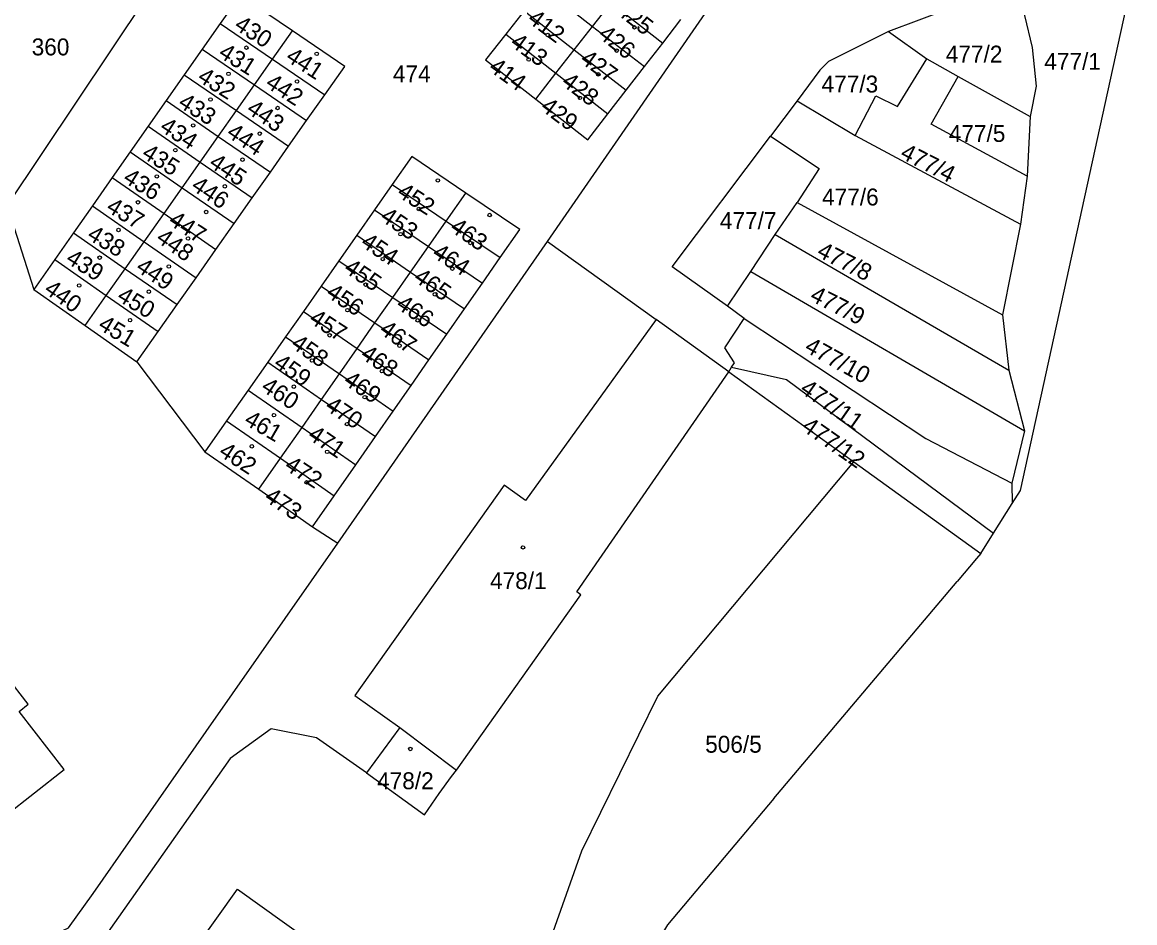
# Model space of a CAD drawing. Extents: x -558358 to -557517, y -1073785 to -1073189.
# Drawn here: x -557909.7 to -557797.9, y -1073433.6 to -1073343.1 of the extents above; entities that cross this region are included whole.
import ezdxf

# ---------------------------------------------------------------- set-up
doc = ezdxf.new("R2010")
doc.units = 0
for name, color, linetype in [('Hranice parcel', 7, 'Continuous'), ('Parcelní čísla', 7, 'Continuous'), ('Značky budov', 7, 'Continuous')]:
    doc.layers.add(name, color=color, linetype=linetype)

msp = doc.modelspace()

# ---------------------------------------------------------------- linework, layer by layer
at = {"layer": 'Hranice parcel'}
for p, q in [((-557911.2, -1073361.51), (-557892.99, -1073334.25)), ((-557809.37, -1073390.13), (-557797.89, -1073337.76)), ((-557809.74, -1073339.14), (-557822.65, -1073343.99)), ((-557857.41, -1073339.54), (-557852.37, -1073343.47)), ((-557852.37, -1073343.47), (-557850.52, -1073341.11)), ((-557850.52, -1073341.11), (-557845.33, -1073345.15)), ((-557859.26, -1073341.9), (-557861.1, -1073344.25)), ((-557859.26, -1073341.9), (-557854.22, -1073345.83)), ((-557845.33, -1073345.15), (-557843.49, -1073342.78)), ((-557889.79, -1073343.18), (-557891.6, -1073345.76)), ((-557889.79, -1073343.18), (-557884.54, -1073346.76)), ((-557884.54, -1073346.76), (-557882.54, -1073343.92)), ((-557854.22, -1073345.83), (-557852.37, -1073343.47)), ((-557852.37, -1073343.47), (-557847.16, -1073347.52)), ((-557861.1, -1073344.25), (-557856.06, -1073348.19)), ((-557822.65, -1073343.99), (-557818.8, -1073346.73)), ((-557891.6, -1073345.76), (-557893.41, -1073348.34)), ((-557891.6, -1073345.76), (-557886.35, -1073349.35)), ((-557856.06, -1073348.19), (-557854.22, -1073345.83)), ((-557854.22, -1073345.83), (-557849, -1073349.9)), ((-557847.16, -1073347.52), (-557845.33, -1073345.15)), ((-557886.35, -1073349.35), (-557884.54, -1073346.76)), ((-557884.54, -1073346.76), (-557879.29, -1073350.34)), ((-557818.8, -1073346.73), (-557815.63, -1073348.5)), ((-557893.41, -1073348.34), (-557895.22, -1073350.93)), ((-557893.41, -1073348.34), (-557888.17, -1073351.94)), ((-557858.09, -1073350.78), (-557856.06, -1073348.19)), ((-557856.06, -1073348.19), (-557850.83, -1073352.27)), ((-557849, -1073349.9), (-557847.16, -1073347.52)), ((-557888.17, -1073351.94), (-557886.35, -1073349.35)), ((-557886.35, -1073349.35), (-557881.11, -1073352.93)), ((-557815.63, -1073348.5), (-557808.41, -1073352.55)), ((-557881.11, -1073352.93), (-557879.29, -1073350.34)), ((-557850.83, -1073352.27), (-557849, -1073349.9)), ((-557895.22, -1073350.93), (-557897.03, -1073353.51)), ((-557895.22, -1073350.93), (-557889.99, -1073354.53)), ((-557831.83, -1073350.97), (-557834.5, -1073354.52)), ((-557831.83, -1073350.97), (-557825.97, -1073354.44)), ((-557889.99, -1073354.53), (-557888.17, -1073351.94)), ((-557888.17, -1073351.94), (-557882.93, -1073355.52)), ((-557808.41, -1073352.55), (-557808.71, -1073358.52)), ((-557897.03, -1073353.51), (-557898.84, -1073356.1)), ((-557897.03, -1073353.51), (-557891.81, -1073357.12)), ((-557882.93, -1073355.52), (-557881.11, -1073352.93)), ((-557891.81, -1073357.12), (-557889.99, -1073354.53)), ((-557889.99, -1073354.53), (-557884.75, -1073358.12)), ((-557825.97, -1073354.44), (-557809.38, -1073363.37)), ((-557898.84, -1073356.1), (-557900.65, -1073358.68)), ((-557898.84, -1073356.1), (-557893.62, -1073359.71)), ((-557884.75, -1073358.12), (-557882.93, -1073355.52)), ((-557893.62, -1073359.71), (-557891.81, -1073357.12)), ((-557891.81, -1073357.12), (-557886.57, -1073360.71)), ((-557886.57, -1073360.71), (-557884.75, -1073358.12)), ((-557900.65, -1073358.68), (-557902.64, -1073361.52)), ((-557900.65, -1073358.68), (-557895.44, -1073362.3)), ((-557872.5, -1073359.38), (-557874.29, -1073361.93)), ((-557872.5, -1073359.38), (-557867.08, -1073363.05)), ((-557808.71, -1073358.52), (-557809.38, -1073363.37)), ((-557895.44, -1073362.3), (-557893.62, -1073359.71)), ((-557893.62, -1073359.71), (-557888.4, -1073363.3)), ((-557867.08, -1073363.05), (-557865.11, -1073360.23)), ((-557911.2, -1073361.51), (-557908.52, -1073369.92)), ((-557902.64, -1073361.52), (-557904.53, -1073364.22)), ((-557902.64, -1073361.52), (-557897.44, -1073365.14)), ((-557888.4, -1073363.3), (-557886.57, -1073360.71)), ((-557834.02, -1073364.39), (-557831.83, -1073361.18)), ((-557831.83, -1073361.18), (-557811.19, -1073372.48)), ((-557897.44, -1073365.14), (-557895.44, -1073362.3)), ((-557895.44, -1073362.3), (-557890.22, -1073365.89)), ((-557874.29, -1073361.93), (-557876.07, -1073364.48)), ((-557874.29, -1073361.93), (-557868.87, -1073365.61)), ((-557890.22, -1073365.89), (-557888.4, -1073363.3)), ((-557868.87, -1073365.61), (-557867.08, -1073363.05)), ((-557867.08, -1073363.05), (-557861.66, -1073366.72)), ((-557809.38, -1073363.37), (-557811.19, -1073372.48)), ((-557904.53, -1073364.22), (-557906.42, -1073366.92)), ((-557904.53, -1073364.22), (-557899.34, -1073367.84)), ((-557899.34, -1073367.84), (-557897.44, -1073365.14)), ((-557897.44, -1073365.14), (-557892.22, -1073368.74)), ((-557877.97, -1073395.43), (-557856.89, -1073365.11)), ((-557876.07, -1073364.48), (-557877.86, -1073367.03)), ((-557876.07, -1073364.48), (-557870.66, -1073368.17)), ((-557856.89, -1073365.11), (-557845.99, -1073372.93)), ((-557836.47, -1073368.11), (-557834.02, -1073364.39)), ((-557834.02, -1073364.39), (-557810.53, -1073378.05)), ((-557892.22, -1073368.74), (-557890.22, -1073365.89)), ((-557870.66, -1073368.17), (-557868.87, -1073365.61)), ((-557868.87, -1073365.61), (-557863.45, -1073369.29)), ((-557906.42, -1073366.92), (-557908.52, -1073369.92)), ((-557906.42, -1073366.92), (-557901.24, -1073370.54)), ((-557877.86, -1073367.03), (-557879.65, -1073369.58)), ((-557877.86, -1073367.03), (-557872.45, -1073370.73)), ((-557863.45, -1073369.29), (-557861.66, -1073366.72)), ((-557901.24, -1073370.54), (-557899.34, -1073367.84)), ((-557899.34, -1073367.84), (-557894.12, -1073371.44)), ((-557872.45, -1073370.73), (-557870.66, -1073368.17)), ((-557870.66, -1073368.17), (-557865.24, -1073371.86)), ((-557838.83, -1073371.62), (-557836.47, -1073368.11)), ((-557836.47, -1073368.11), (-557808.98, -1073384.15)), ((-557894.12, -1073371.44), (-557892.22, -1073368.74)), ((-557879.65, -1073369.58), (-557881.44, -1073372.13)), ((-557879.65, -1073369.58), (-557874.24, -1073373.29)), ((-557865.24, -1073371.86), (-557863.45, -1073369.29)), ((-557908.52, -1073369.92), (-557903.35, -1073373.55)), ((-557903.35, -1073373.55), (-557901.24, -1073370.54)), ((-557901.24, -1073370.54), (-557896.03, -1073374.15)), ((-557874.24, -1073373.29), (-557872.45, -1073370.73)), ((-557872.45, -1073370.73), (-557867.03, -1073374.43)), ((-557896.03, -1073374.15), (-557894.12, -1073371.44)), ((-557867.03, -1073374.43), (-557865.24, -1073371.86)), ((-557837.14, -1073372.84), (-557838.83, -1073371.62)), ((-557881.44, -1073372.13), (-557883.23, -1073374.68)), ((-557881.44, -1073372.13), (-557876.02, -1073375.85)), ((-557838.68, -1073378.19), (-557845.99, -1073372.93)), ((-557837.14, -1073372.84), (-557818.89, -1073384.91)), ((-557811.19, -1073372.48), (-557810.53, -1073378.05)), ((-557903.35, -1073373.55), (-557898.17, -1073377.19)), ((-557876.02, -1073375.85), (-557874.24, -1073373.29)), ((-557874.24, -1073373.29), (-557868.82, -1073377.01)), ((-557898.17, -1073377.19), (-557896.03, -1073374.15)), ((-557883.23, -1073374.68), (-557885.02, -1073377.23)), ((-557883.23, -1073374.68), (-557877.81, -1073378.41)), ((-557868.82, -1073377.01), (-557867.03, -1073374.43)), ((-557877.81, -1073378.41), (-557876.02, -1073375.85)), ((-557876.02, -1073375.85), (-557870.61, -1073379.58)), ((-557898.17, -1073377.19), (-557891.33, -1073386.24)), ((-557885.02, -1073377.23), (-557886.99, -1073380.04)), ((-557885.02, -1073377.23), (-557879.6, -1073380.98)), ((-557870.61, -1073379.58), (-557868.82, -1073377.01)), ((-557879.6, -1073380.98), (-557877.81, -1073378.41)), ((-557877.81, -1073378.41), (-557872.4, -1073382.15)), ((-557838.68, -1073378.19), (-557838.4, -1073377.75)), ((-557838.68, -1073378.19), (-557826.12, -1073387.26)), ((-557810.53, -1073378.05), (-557808.98, -1073384.15)), ((-557872.4, -1073382.15), (-557870.61, -1073379.58)), ((-557886.99, -1073380.04), (-557889.16, -1073383.14)), ((-557886.99, -1073380.04), (-557881.57, -1073383.79)), ((-557881.57, -1073383.79), (-557879.6, -1073380.98)), ((-557879.6, -1073380.98), (-557874.19, -1073384.72)), ((-557874.19, -1073384.72), (-557872.4, -1073382.15)), ((-557889.16, -1073383.14), (-557891.33, -1073386.24)), ((-557889.16, -1073383.14), (-557883.75, -1073386.9)), ((-557883.75, -1073386.9), (-557881.57, -1073383.79)), ((-557881.57, -1073383.79), (-557876.16, -1073387.55)), ((-557808.98, -1073384.15), (-557810.24, -1073389.4)), ((-557876.16, -1073387.55), (-557874.19, -1073384.72)), ((-557818.89, -1073384.91), (-557810.24, -1073389.4)), ((-557891.33, -1073386.24), (-557885.92, -1073390.01)), ((-557885.92, -1073390.01), (-557883.75, -1073386.9)), ((-557883.75, -1073386.9), (-557878.33, -1073390.67)), ((-557826.12, -1073387.26), (-557813.37, -1073396.47)), ((-557878.33, -1073390.67), (-557876.16, -1073387.55)), ((-557810.24, -1073389.4), (-557810.21, -1073391.46)), ((-557885.92, -1073390.01), (-557880.51, -1073393.79)), ((-557880.51, -1073393.79), (-557878.33, -1073390.67)), ((-557810.21, -1073391.46), (-557809.37, -1073390.13)), ((-557812.08, -1073394.43), (-557810.21, -1073391.46)), ((-557880.51, -1073393.79), (-557877.97, -1073395.43)), ((-557813.37, -1073396.47), (-557812.08, -1073394.43)), ((-557813.37, -1073396.47), (-557813.79, -1073396.96)), ((-557813.79, -1073396.96), (-557815.73, -1073399.27)), ((-557834.15, -1073421.11), (-557815.73, -1073399.27)), ((-557871.76, -1073413.96), (-557875.08, -1073418.52)), ((-557871.76, -1073413.96), (-557866.06, -1073418.25))]:
    msp.add_line(p, q, dxfattribs=at)
for points in [[(-558022.09, -1073311.21), (-558020.08, -1073313.87), (-558000.41, -1073328.2), (-557993.92, -1073334.5), (-557986.04, -1073343.93), (-557967.1, -1073369.2), (-557918.24, -1073434.51), (-557914.64, -1073436.24), (-557909.55, -1073436.22), (-557905.05, -1073434.1), (-557902.57, -1073430.65), (-557891.22, -1073414.37), (-557877.97, -1073395.43)], [(-557856.89, -1073365.11), (-557824.85, -1073318.68), (-557819.71, -1073312.13)], [(-557809.74, -1073339.14), (-557808.21, -1073345.61), (-557807.79, -1073349.5), (-557808.41, -1073352.55)], [(-557882.54, -1073343.92), (-557887.8, -1073340.34), (-557889.79, -1073343.18)], [(-557879.29, -1073350.34), (-557877.28, -1073347.5), (-557882.54, -1073343.92)], [(-557861.1, -1073344.25), (-557863.13, -1073346.85), (-557858.09, -1073350.78)], [(-557822.65, -1073343.99), (-557828.66, -1073347), (-557829.52, -1073347.89), (-557831.83, -1073350.97)], [(-557825.97, -1073354.44), (-557823.9, -1073350.44), (-557821.72, -1073351.54), (-557818.8, -1073346.73)], [(-557808.71, -1073358.52), (-557818.34, -1073353.3), (-557815.63, -1073348.5)], [(-557858.09, -1073350.78), (-557852.85, -1073354.88), (-557850.83, -1073352.27)], [(-557838.83, -1073371.62), (-557844.36, -1073367.66), (-557834.5, -1073354.52)], [(-557834.5, -1073354.52), (-557829.59, -1073357.77), (-557831.83, -1073361.18)], [(-557865.11, -1073360.23), (-557870.53, -1073356.57), (-557872.5, -1073359.38)], [(-557861.66, -1073366.72), (-557859.69, -1073363.89), (-557865.11, -1073360.23)], [(-557845.99, -1073372.93), (-557859.12, -1073391.15), (-557861.27, -1073389.6), (-557876.27, -1073410.74), (-557871.76, -1073413.96)], [(-557838.4, -1073377.75), (-557838.12, -1073377.3), (-557839.1, -1073375.8), (-557837.14, -1073372.84)], [(-557866.06, -1073418.25), (-557853.54, -1073400.64), (-557853.96, -1073400.34), (-557838.68, -1073378.19)], [(-557838.4, -1073377.75), (-557832.9, -1073378.99), (-557812.08, -1073394.43)], [(-557861.36, -1073465.07), (-557859.38, -1073443.12), (-557853.44, -1073426.35), (-557845.8, -1073410.81), (-557826.12, -1073387.26)], [(-557930.26, -1073400.48), (-557932.35, -1073402.1), (-557927.81, -1073407.96), (-557928.68, -1073408.63), (-557926.46, -1073411.51), (-557925.59, -1073410.83), (-557921.19, -1073416.52), (-557922.06, -1073417.2), (-557919.87, -1073420.02), (-557919, -1073419.35), (-557914.46, -1073425.22), (-557905.47, -1073418.2), (-557910.01, -1073412.34), (-557909.08, -1073411.62), (-557911.27, -1073408.79), (-557912.2, -1073409.51), (-557916.62, -1073403.8), (-557915.7, -1073403.08), (-557917.89, -1073400.24), (-557918.82, -1073400.96), (-557923.37, -1073395.09)], [(-557875.08, -1073418.52), (-557880.11, -1073415), (-557884.66, -1073414.11), (-557888.78, -1073417.07), (-557919.08, -1073460.09), (-557919.51, -1073465.45), (-557958.15, -1073519.56), (-557960.76, -1073525.37), (-557961.25, -1073531.9), (-557959.85, -1073543.64), (-557958.52, -1073546.41), (-557955.67, -1073549.33), (-557941.9, -1073559.58)], [(-557875.08, -1073418.52), (-557869.25, -1073422.74), (-557867.79, -1073420.61), (-557866.54, -1073418.89), (-557866.06, -1073418.25)], [(-557834.15, -1073421.11), (-557844.86, -1073433.81), (-557856.07, -1073452.41), (-557861.36, -1073465.07)], [(-557902.93, -1073455.63), (-557905.05, -1073454), (-557900.72, -1073447.94), (-557901.66, -1073447.27), (-557899.55, -1073444.33), (-557898.62, -1073444.99), (-557894.46, -1073439.18), (-557895.4, -1073438.51), (-557893.33, -1073435.61), (-557892.39, -1073436.28), (-557888.07, -1073430.23), (-557878.84, -1073436.82), (-557883.15, -1073442.9), (-557882.08, -1073443.65), (-557884.22, -1073446.66), (-557885.28, -1073445.91), (-557889.41, -1073451.73), (-557888.35, -1073452.48), (-557890.43, -1073455.41), (-557891.49, -1073454.66), (-557895.8, -1073460.74)]]:
    msp.add_lwpolyline(points, dxfattribs=at)
at = {"layer": 'Značky budov'}
for centre in [(-557848.17, -1073343.57), (-557856.88, -1073344.34), (-557887.16, -1073345.62), (-557880.1, -1073346.24), (-557849.95, -1073345.91), (-557858.79, -1073346.8), (-557888.96, -1073348.25), (-557851.8, -1073348.3), (-557882.07, -1073349.01), (-557853.64, -1073350.66), (-557890.77, -1073350.82), (-557884.03, -1073351.68), (-557892.51, -1073353.43), (-557885.82, -1073354.26), (-557894.3, -1073355.92), (-557887.55, -1073356.88), (-557896.16, -1073358.56), (-557889.33, -1073359.55), (-557867.93, -1073358.96), (-557898.05, -1073361.16), (-557869.83, -1073361.84), (-557891.21, -1073362.13), (-557862.71, -1073362.44), (-557900.02, -1073363.95), (-557893.03, -1073364.8), (-557871.67, -1073364.36), (-557864.65, -1073365.25), (-557901.91, -1073366.72), (-557873.46, -1073366.87), (-557894.96, -1073367.61), (-557866.46, -1073367.83), (-557903.97, -1073369.53), (-557875.18, -1073369.44), (-557896.97, -1073370.15), (-557868.22, -1073370.41), (-557877.01, -1073372.01), (-557898.85, -1073373.01), (-557869.95, -1073373.03), (-557878.79, -1073374.53), (-557871.78, -1073375.57), (-557880.58, -1073377.07), (-557873.54, -1073378.14), (-557882.4, -1073379.7), (-557875.27, -1073380.75), (-557884.39, -1073382.56), (-557877.05, -1073383.46), (-557886.62, -1073385.7), (-557879.05, -1073386.25), (-557881.11, -1073389.32), (-557859.37, -1073395.86), (-557870.69, -1073416.12)]:
    msp.add_circle(centre, 0.175, dxfattribs=at)

# ---------------------------------------------------------------- texts
at = {"layer": 'Parcelní čísla'}
for s, rotation, p in [('425', 322, (-557850.11, -1073342.12)), ('430', 327, (-557888.49, -1073343.66)), ('412', 323, (-557859.02, -1073342.96)), ('426', 321, (-557851.91, -1073344.49)), ('413', 324, (-557860.76, -1073345.36)), ('431', 328, (-557890.08, -1073346.47)), ('441', 327, (-557883.32, -1073346.85)), ('427', 324, (-557853.74, -1073347.03)), ('414', 324, (-557862.92, -1073347.85)), ('432', 328, (-557892.19, -1073348.9)), ('428', 323, (-557855.61, -1073349.29)), ('442', 327, (-557885.36, -1073349.49)), ('433', 328, (-557894.13, -1073351.48)), ('443', 326, (-557887.26, -1073352.08)), ('429', 323, (-557857.71, -1073351.8)), ('434', 327, (-557895.98, -1073353.89)), ('444', 326, (-557889.27, -1073354.46)), ('435', 328, (-557897.79, -1073356.58)), ('477/4', 333, (-557821.57, -1073356.66)), ('445', 326, (-557891.04, -1073357.5)), ('436', 328, (-557899.67, -1073359.04)), ('446', 326, (-557892.82, -1073359.8)), ('452', 327, (-557872.13, -1073360.48)), ('437', 329, (-557901.36, -1073362)), ('447', 327, (-557895.11, -1073363.31)), ('453', 326, (-557873.82, -1073362.91)), ('438', 329, (-557903.28, -1073364.79)), ('463', 325, (-557866.82, -1073363.96)), ('448', 325, (-557896.35, -1073365.03)), ('454', 326, (-557875.78, -1073365.49)), ('439', 328, (-557905.42, -1073367.16)), ('464', 327, (-557868.6, -1073366.58)), ('477/8', 333, (-557829.94, -1073366.55)), ('449', 326, (-557898.38, -1073367.98)), ('455', 326, (-557877.48, -1073368.08)), ('465', 325, (-557870.46, -1073369)), ('440', 325, (-557907.6, -1073370.19)), ('456', 326, (-557879.26, -1073370.56)), ('450', 329, (-557900.28, -1073370.96)), ('466', 326, (-557872.22, -1073371.73)), ('477/9', 333, (-557830.64, -1073370.98)), ('451', 329, (-557902.18, -1073373.84)), ('457', 327, (-557880.97, -1073373.18)), ('467', 324, (-557873.92, -1073374.23)), ('458', 325, (-557882.8, -1073375.67)), ('477/10', 331, (-557831.18, -1073376.1)), ('468', 326, (-557875.81, -1073376.75)), ('459', 325, (-557884.54, -1073377.63)), ('469', 326, (-557877.52, -1073379.37)), ('460', 327, (-557885.79, -1073380.03)), ('477/11', 325, (-557831.64, -1073380.2)), ('470', 326, (-557879.37, -1073381.93)), ('461', 330, (-557887.5, -1073383.42)), ('477/12', 325, (-557831.47, -1073384)), ('471', 326, (-557881.11, -1073384.86)), ('462', 327, (-557890.05, -1073386.55)), ('472', 327, (-557883.44, -1073387.95)), ('473', 326, (-557885.47, -1073391.09))]:
    msp.add_text(s, height=1.7, rotation=rotation, dxfattribs=at).set_placement(p)
for s, p in [('360', (-557908.74, -1073346.39)), ('477/2', (-557816.88, -1073347.11)), ('477/1', (-557806.98, -1073347.84)), ('474', (-557872.44, -1073349.09)), ('477/3', (-557829.36, -1073350.12)), ('477/5', (-557816.58, -1073355.09)), ('477/6', (-557829.31, -1073361.48)), ('477/7', (-557839.58, -1073363.85)), ('478/1', (-557862.68, -1073400.05)), ('506/5', (-557841.06, -1073416.5)), ('478/2', (-557874.03, -1073420.17))]:
    msp.add_text(s, height=1.7, dxfattribs=at).set_placement(p)

doc.saveas('drawing.dxf')
